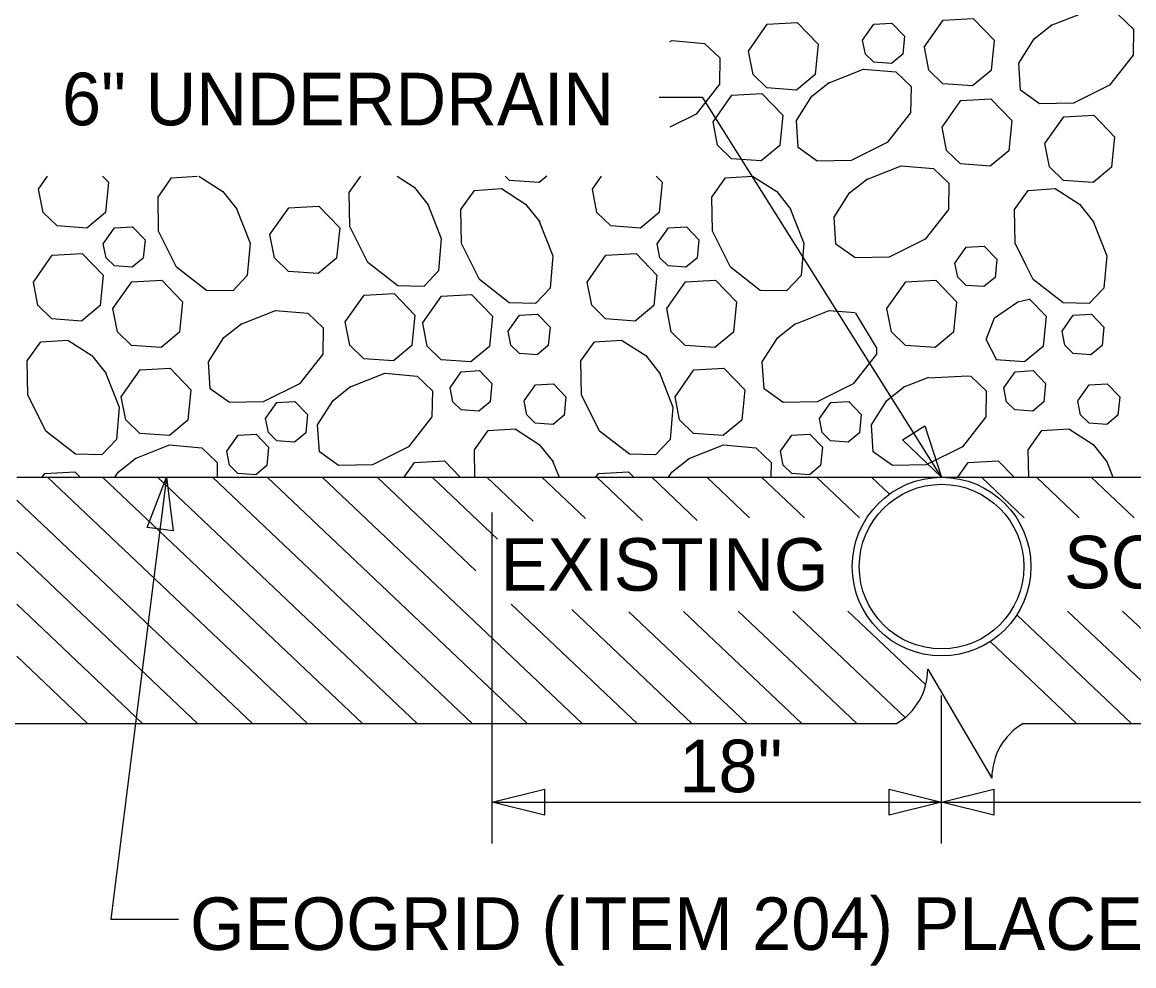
# Model space of a CAD drawing. Extents: x 0 to 34, y 0 to 22.
# Drawn here: x 2.911 to 6.22, y 13.612 to 16.421 of the extents above; entities that cross this region are included whole.
import ezdxf

# ---------------------------------------------------------------- set-up
doc = ezdxf.new("R2010")
doc.units = 0
doc.layers.add('Default', color=7, linetype='Continuous')

msp = doc.modelspace()

# ---------------------------------------------------------------- linework, layer by layer
at = {"layer": 'Default'}
for p, q in [((4.8073, 16.1983), (4.9363, 16.1983)), ((5.6483, 15.0663), (4.9363, 16.1983)), ((5.8062, 15.541), (5.8754, 15.5885)), ((5.8754, 15.5885), (5.9095, 15.5963)), ((5.3917, 15.5546), (5.4536, 15.4524)), ((5.7807, 15.4765), (5.8062, 15.541)), ((5.8123, 15.4145), (5.7807, 15.4765)), ((5.6103, 15.3624), (5.7257, 15.3685)), ((2.8946, 15.0663), (8.1508, 15.0663)), ((2.9861, 15.0663), (3.76, 14.3331)), ((3.1497, 15.0663), (3.9236, 14.3331)), ((3.3407, 15.0663), (3.175, 13.7508)), ((3.3133, 15.0663), (4.0872, 14.3331)), ((3.4769, 15.0663), (4.2507, 14.3331)), ((3.6404, 15.0663), (4.4143, 14.3331)), ((3.804, 15.0663), (4.5779, 14.3331)), ((3.9676, 15.0663), (4.2618, 14.7875)), ((4.1311, 15.0663), (4.3256, 14.8821)), ((4.2947, 15.0663), (4.4322, 14.936)), ((4.4583, 15.0663), (4.5881, 14.9433)), ((4.6218, 15.0663), (4.7573, 14.938)), ((4.7854, 15.0663), (4.9209, 14.938)), ((4.949, 15.0663), (5.0766, 14.9455)), ((5.1125, 15.0663), (5.2401, 14.9455)), ((5.2761, 15.0663), (5.4037, 14.9455)), ((5.4397, 15.0663), (5.4927, 15.0161)), ((5.7668, 15.0663), (5.8944, 14.9455)), ((5.9304, 15.0663), (6.058, 14.9455)), ((6.094, 15.0663), (6.2215, 14.9455)), ((2.8946, 14.9981), (3.5965, 14.3331)), ((4.3102, 13.9764), (4.3102, 14.9613)), ((2.8946, 14.8432), (3.4329, 14.3331)), ((2.8946, 14.6882), (3.2693, 14.3331)), ((4.3667, 14.6882), (4.7414, 14.3331)), ((4.547, 14.6723), (4.905, 14.3331)), ((4.7173, 14.6659), (5.0686, 14.3331)), ((4.8799, 14.6669), (5.2321, 14.3331)), ((5.0421, 14.6681), (5.3957, 14.3331)), ((5.2057, 14.6681), (5.5401, 14.3513)), ((5.3693, 14.6681), (5.6012, 14.4484)), ((6.0235, 14.6681), (6.3771, 14.3331)), ((6.1871, 14.6681), (6.5407, 14.3331)), ((5.8722, 14.6566), (6.2136, 14.3331)), ((5.7927, 14.5769), (6.05, 14.3331)), ((2.8946, 14.5332), (3.1057, 14.3331)), ((5.6072, 14.4954), (5.7979, 14.1708)), ((5.6483, 13.9764), (5.6483, 14.4163)), ((2.7025, 14.3331), (5.5143, 14.3331)), ((5.8908, 14.3331), (8.3429, 14.3331)), ((4.3102, 14.0989), (6.9864, 14.0989)), ((4.3102, 14.0989), (4.6442, 14.0989)), ((5.6483, 14.0989), (5.6141, 14.0989)), ((5.6483, 14.0989), (5.9823, 14.0989)), ((3.175, 13.7508), (3.3759, 13.7508))]:
    msp.add_line(p, q, dxfattribs=at)
for points in [[(5.9727, 16.4109), (6.0776, 16.4524), (6.1738, 16.4441), (6.2196, 16.4006), (6.2182, 16.3225), (6.1487, 16.2337), (6.0414, 16.18), (5.9402, 16.1783), (5.8833, 16.2188), (5.8779, 16.2993), (5.9241, 16.3714), (5.977, 16.4136)], [(5.0733, 16.335), (5.1293, 16.4148), (5.2187, 16.4199), (5.2809, 16.3554), (5.2719, 16.265), (5.2167, 16.2191), (5.1284, 16.2255), (5.0868, 16.2658), (5.0733, 16.335)], [(5.4132, 16.3678), (5.4468, 16.4156), (5.5005, 16.4187), (5.5378, 16.38), (5.5324, 16.3258), (5.4993, 16.2983), (5.4462, 16.3021), (5.4213, 16.3263), (5.4132, 16.3678)], [(5.5968, 16.3472), (5.6528, 16.4269), (5.7423, 16.432), (5.8044, 16.3675), (5.7954, 16.2772), (5.7402, 16.2312), (5.6519, 16.2376), (5.6103, 16.2779), (5.5969, 16.3472)], [(4.8391, 16.3636), (4.8462, 16.3664), (4.9424, 16.3581), (4.9882, 16.3146), (4.9867, 16.2365), (4.9173, 16.1477), (4.8391, 16.1086)], [(5.3107, 16.2401), (5.4155, 16.2817), (5.5118, 16.2733), (5.5576, 16.2298), (5.5561, 16.1517), (5.4867, 16.063), (5.3793, 16.0093), (5.2782, 16.0075), (5.2212, 16.048), (5.2159, 16.1285), (5.2621, 16.2006), (5.315, 16.2428)], [(4.9679, 16.1242), (5.0239, 16.2039), (5.1133, 16.209), (5.1755, 16.1445), (5.1665, 16.0542), (5.1113, 16.0083), (5.0229, 16.0147), (4.9814, 16.055), (4.9679, 16.1242)], [(5.6495, 16.1086), (5.7055, 16.1883), (5.795, 16.1934), (5.8572, 16.1289), (5.8482, 16.0386), (5.7929, 15.9926), (5.7046, 15.999), (5.6631, 16.0393), (5.6496, 16.1086)], [(5.9558, 16.0598), (6.0118, 16.1395), (6.1013, 16.1446), (6.1634, 16.0801), (6.1544, 15.9898), (6.0992, 15.9438), (6.0109, 15.9502), (5.9694, 15.9905), (5.9559, 16.0598)], [(5.423, 15.9523), (5.5278, 15.9939), (5.6241, 15.9856), (5.6699, 15.9421), (5.6684, 15.8639), (5.5989, 15.7752), (5.4917, 15.7215), (5.3905, 15.7197), (5.3336, 15.7602), (5.3282, 15.8407), (5.3744, 15.9128), (5.4273, 15.955)], [(2.9597, 15.9243), (2.9866, 15.9625)], [(3.15, 15.9625), (3.1674, 15.9446), (3.1584, 15.8543), (3.1031, 15.8083), (3.0148, 15.8147), (2.9732, 15.855), (2.9597, 15.9243)], [(3.5478, 15.868), (3.5894, 15.7632), (3.581, 15.6669), (3.5375, 15.6211), (3.4594, 15.6226), (3.3707, 15.692), (3.317, 15.7994), (3.3152, 15.9005), (3.3557, 15.9575), (3.432, 15.9625)], [(3.4367, 15.9625), (3.5083, 15.9167), (3.5505, 15.8638)], [(4.1172, 15.8815), (4.1587, 15.7768), (4.1504, 15.6805), (4.1069, 15.6347), (4.0288, 15.6362), (3.94, 15.7056), (3.8864, 15.813), (3.8846, 15.9141), (3.919, 15.9625)], [(4.0273, 15.9625), (4.0777, 15.9303), (4.1199, 15.8773)], [(4.4728, 15.9625), (4.4503, 15.9438), (4.362, 15.9502), (4.3493, 15.9625)], [(4.6086, 15.9243), (4.6355, 15.9625)], [(4.7989, 15.9625), (4.8163, 15.9446), (4.8073, 15.8543), (4.752, 15.8083), (4.6637, 15.8147), (4.6222, 15.855), (4.6087, 15.9243)], [(5.1967, 15.868), (5.2383, 15.7632), (5.2299, 15.6669), (5.1864, 15.6211), (5.1083, 15.6226), (5.0196, 15.692), (4.9659, 15.7994), (4.9641, 15.9005), (5.0046, 15.9575), (5.0852, 15.9628), (5.1572, 15.9167), (5.1994, 15.8638)], [(4.4493, 15.8307), (4.4909, 15.7259), (4.4826, 15.6296), (4.4391, 15.5839), (4.3609, 15.5853), (4.2722, 15.6548), (4.2185, 15.7621), (4.2167, 15.8633), (4.2572, 15.9202), (4.3377, 15.9256), (4.4098, 15.8794), (4.452, 15.8265)], [(5.8998, 15.6974), (5.8674, 15.7621), (5.8657, 15.8633), (5.9061, 15.9202), (5.9867, 15.9256), (6.0587, 15.8794), (6.1009, 15.8265)], [(3.6484, 15.7887), (3.7044, 15.8684), (3.7939, 15.8735), (3.8561, 15.809), (3.8471, 15.7187), (3.7919, 15.6728), (3.7035, 15.6791), (3.662, 15.7194), (3.6485, 15.7887)], [(6.0982, 15.8307), (6.1398, 15.7259), (6.1315, 15.6296), (6.088, 15.5839), (6.0099, 15.5853), (5.9211, 15.6548), (5.9002, 15.6966)], [(3.1522, 15.761), (3.1858, 15.8088), (3.2395, 15.8119), (3.2768, 15.7732), (3.2714, 15.719), (3.2382, 15.6914), (3.1852, 15.6953), (3.1603, 15.7194), (3.1522, 15.761)], [(4.8011, 15.761), (4.8347, 15.8088), (4.8884, 15.8119), (4.9257, 15.7732), (4.9203, 15.719), (4.8872, 15.6914), (4.8342, 15.6953), (4.8092, 15.7194), (4.8012, 15.761)], [(5.688, 15.7035), (5.7217, 15.7513), (5.7753, 15.7544), (5.8127, 15.7156), (5.8073, 15.6615), (5.7741, 15.6339), (5.7211, 15.6377), (5.6962, 15.6619), (5.6881, 15.7034)], [(2.944, 15.6475), (3, 15.7272), (3.0895, 15.7323), (3.1517, 15.6679), (3.1427, 15.5775), (3.0874, 15.5315), (2.9991, 15.538), (2.9575, 15.5783), (2.9441, 15.6475)], [(4.5929, 15.6475), (4.6489, 15.7272), (4.7384, 15.7323), (4.8006, 15.6679), (4.7916, 15.5775), (4.7363, 15.5315), (4.648, 15.538), (4.6064, 15.5783), (4.593, 15.6475)], [(3.1807, 15.5684), (3.2368, 15.6481), (3.3262, 15.6532), (3.3884, 15.5888), (3.3794, 15.4984), (3.3242, 15.4524), (3.2358, 15.4588), (3.1943, 15.4991), (3.1808, 15.5684)], [(4.8297, 15.5684), (4.8857, 15.6481), (4.9751, 15.6532), (5.0373, 15.5888), (5.0283, 15.4984), (4.9731, 15.4524), (4.8847, 15.4588), (4.8432, 15.4991), (4.8297, 15.5684)], [(5.4853, 15.5684), (5.5413, 15.6481), (5.6307, 15.6532), (5.6929, 15.5888), (5.6839, 15.4984), (5.6287, 15.4524), (5.5404, 15.4588), (5.4988, 15.4991), (5.4853, 15.5684)], [(3.8727, 15.5289), (3.9287, 15.6086), (4.0181, 15.6137), (4.0803, 15.5493), (4.0713, 15.4589), (4.016, 15.413), (3.9277, 15.4193), (3.8862, 15.4596), (3.8727, 15.5289)], [(4.1031, 15.5255), (4.1591, 15.6052), (4.2486, 15.6103), (4.3108, 15.5458), (4.3018, 15.4555), (4.2465, 15.4095), (4.1582, 15.416), (4.1167, 15.4563), (4.1032, 15.5255)], [(5.9095, 15.5979), (5.9597, 15.5458), (5.9507, 15.4555), (5.8954, 15.4095), (5.8102, 15.4157)], [(3.5602, 15.5216), (3.6649, 15.5632), (3.7612, 15.5548), (3.807, 15.5113), (3.8055, 15.4332), (3.7361, 15.3445), (3.6287, 15.2908), (3.5276, 15.289), (3.4707, 15.3295), (3.4653, 15.41), (3.5115, 15.4821), (3.5644, 15.5243)], [(5.2091, 15.5216), (5.3139, 15.5632), (5.3908, 15.5565)], [(4.358, 15.5009), (4.3916, 15.5487), (4.4453, 15.5518), (4.4826, 15.5131), (4.4772, 15.4589), (4.4441, 15.4313), (4.3911, 15.4352), (4.3661, 15.4593), (4.358, 15.5009)], [(5.4548, 15.4535), (5.4544, 15.4332), (5.385, 15.3445), (5.2777, 15.2908), (5.1765, 15.289), (5.1196, 15.3295), (5.1142, 15.41), (5.1604, 15.4821), (5.2133, 15.5243)], [(6.0069, 15.5009), (6.0405, 15.5487), (6.0942, 15.5518), (6.1315, 15.5131), (6.1261, 15.4589), (6.093, 15.4313), (6.04, 15.4352), (6.015, 15.4593), (6.0069, 15.5009)], [(3.158, 15.38), (3.1996, 15.2752), (3.1913, 15.1789), (3.1478, 15.1331), (3.0697, 15.1346), (2.9809, 15.204), (2.9272, 15.3113), (2.9254, 15.4125), (2.9659, 15.4694), (3.0465, 15.4748), (3.1185, 15.4286), (3.1607, 15.3757)], [(4.8069, 15.38), (4.8485, 15.2752), (4.8402, 15.1789), (4.7967, 15.1331), (4.7186, 15.1346), (4.6298, 15.204), (4.5762, 15.3113), (4.5744, 15.4125), (4.6148, 15.4694), (4.6954, 15.4748), (4.7674, 15.4286), (4.8097, 15.3757)], [(3.2057, 15.3062), (3.2617, 15.3859), (3.3512, 15.391), (3.4133, 15.3265), (3.4043, 15.2362), (3.3491, 15.1903), (3.2607, 15.1966), (3.2192, 15.2369), (3.2057, 15.3062)], [(4.8546, 15.3062), (4.9106, 15.3859), (5.0001, 15.391), (5.0622, 15.3265), (5.0532, 15.2362), (4.998, 15.1903), (4.9097, 15.1966), (4.8681, 15.2369), (4.8546, 15.3062)], [(3.8853, 15.3344), (3.9901, 15.376), (4.0864, 15.3676), (4.1322, 15.3241), (4.1307, 15.246), (4.0612, 15.1572), (3.9539, 15.1036), (3.8528, 15.1018), (3.7958, 15.1423), (3.7904, 15.2228), (3.8366, 15.2949), (3.8895, 15.3371)], [(4.1846, 15.3328), (4.2182, 15.3806), (4.2719, 15.3837), (4.3092, 15.345), (4.3038, 15.2908), (4.2707, 15.2632), (4.2177, 15.267), (4.1927, 15.2912), (4.1847, 15.3328)], [(5.7255, 15.3685), (5.7353, 15.3676), (5.7811, 15.3241), (5.7796, 15.246), (5.7102, 15.1572), (5.6028, 15.1036), (5.5017, 15.1018), (5.4447, 15.1423), (5.4394, 15.2228), (5.4855, 15.2949), (5.5384, 15.3371)], [(5.5342, 15.3344), (5.6098, 15.3644)], [(5.8335, 15.3328), (5.8672, 15.3806), (5.9208, 15.3837), (5.9581, 15.345), (5.9527, 15.2908), (5.9196, 15.2632), (5.8666, 15.267), (5.8417, 15.2912), (5.8336, 15.3328)], [(4.4053, 15.2934), (4.4389, 15.3412), (4.4926, 15.3443), (4.5299, 15.3055), (4.5245, 15.2514), (4.4914, 15.2238), (4.4384, 15.2276), (4.4134, 15.2518), (4.4053, 15.2933)], [(6.0542, 15.2934), (6.0878, 15.3412), (6.1415, 15.3443), (6.1788, 15.3055), (6.1734, 15.2514), (6.1403, 15.2238), (6.0873, 15.2276), (6.0623, 15.2518), (6.0542, 15.2933)], [(3.6356, 15.2408), (3.6692, 15.2887), (3.7229, 15.2917), (3.7602, 15.253), (3.7548, 15.1988), (3.7216, 15.1713), (3.6686, 15.1751), (3.6437, 15.1993), (3.6356, 15.2408)], [(5.2845, 15.2408), (5.3181, 15.2887), (5.3718, 15.2917), (5.4091, 15.253), (5.4037, 15.1988), (5.3705, 15.1713), (5.3175, 15.1751), (5.2926, 15.1993), (5.2845, 15.2408)], [(3.52, 15.1436), (3.5536, 15.1915), (3.6073, 15.1945), (3.6446, 15.1558), (3.6392, 15.1016), (3.606, 15.074), (3.553, 15.0779), (3.5281, 15.102), (3.52, 15.1436)], [(4.2588, 15.0663), (4.2574, 15.1481), (4.2978, 15.2051), (4.3784, 15.2105), (4.4504, 15.1643), (4.4927, 15.1114)], [(5.1689, 15.1436), (5.2025, 15.1915), (5.2562, 15.1945), (5.2935, 15.1558), (5.2881, 15.1016), (5.2549, 15.074), (5.2019, 15.0779), (5.177, 15.102), (5.1689, 15.1436)], [(5.9077, 15.0663), (5.9063, 15.1481), (5.9467, 15.2051), (6.0273, 15.2105), (6.0994, 15.1643), (6.1416, 15.1114)], [(3.2448, 15.1209), (3.3497, 15.1625), (3.4459, 15.1541), (3.4917, 15.1106), (3.4908, 15.0663)], [(4.8937, 15.1209), (4.9986, 15.1625), (5.0948, 15.1541), (5.1406, 15.1106), (5.1397, 15.0663)], [(3.1865, 15.0663), (3.1962, 15.0814), (3.2491, 15.1236)], [(4.0479, 15.0663), (4.0786, 15.1099), (4.168, 15.115), (4.215, 15.0663)], [(4.4899, 15.1156), (4.5095, 15.0663)], [(4.8354, 15.0663), (4.8451, 15.0814), (4.898, 15.1236)], [(5.6969, 15.0663), (5.7275, 15.1099), (5.8169, 15.115), (5.8639, 15.0663)], [(6.1389, 15.1156), (6.1584, 15.0663)], [(2.9698, 15.0663), (2.9778, 15.0778), (3.0672, 15.0828), (3.0832, 15.0663)], [(4.6187, 15.0663), (4.6267, 15.0778), (4.7162, 15.0828), (4.7321, 15.0663)]]:
    msp.add_lwpolyline(points, dxfattribs=at)
for points in [[(5.5983, 15.2191), (5.6483, 15.0663), (5.5322, 15.1776)], [(3.2826, 14.9164), (3.3407, 15.0663), (3.3599, 14.9067)], [(4.4662, 14.0599), (4.3102, 14.0989), (4.4662, 14.1379)], [(5.4923, 14.1379), (5.6483, 14.0989), (5.4923, 14.0599)], [(5.8043, 14.0599), (5.6483, 14.0989), (5.8043, 14.1379)]]:
    msp.add_lwpolyline(points, close=True, dxfattribs=at)
for radius in [0.266, 0.266, 0.266, 0.2451]:
    msp.add_circle((5.6483, 14.8003), radius, dxfattribs=at)
for centre, start, end in [((5.419, 14.4954), 300.4422, 360), ((5.9861, 14.1708), 120.4422, 180)]:
    msp.add_arc(centre, 0.1882, start, end, dxfattribs=at)

# ---------------------------------------------------------------- texts
for s, height, p in [('6" UNDERDRAIN', 0.156486, (3.0292, 16.1141)), ('SOILS', 0.15649, (6.0129, 14.7356)), ('EXISTING', 0.15649, (4.335, 14.7285)), ('18"', 0.15649, (4.8674, 14.1285)), ('GEOGRID (ITEM 204) PLACED ON ', 0.156486, (3.4104, 13.659))]:
    msp.add_text(s, height=height, rotation=360, dxfattribs=at).set_placement(p)

doc.saveas('drawing.dxf')
